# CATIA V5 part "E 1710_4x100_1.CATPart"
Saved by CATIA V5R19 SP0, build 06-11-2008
Part number: E 1710_4x100_1
Definition: E 1710_4x100_1
Nomenclature: E 1710_4x100_1
Source: Unknown
Description: PART-E 1710_4x100_1-DESC
Bounding box of the stored display mesh (mm): x -4 to 4, y -3.991 to 3.991, z 0 to 93.427
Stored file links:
  C:\Users\jsmid\Desktop\DP_Smidak_Forma LEGO\E 1710_4x100_1.CATPart
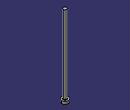
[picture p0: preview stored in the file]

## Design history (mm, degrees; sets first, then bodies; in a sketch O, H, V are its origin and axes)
Body1 "E 1710_4x100" (main body)
  Solid1: solid without history
  Sketch1 on face of Solid1, origin (0, 0, 100), H (1, 0, 0), V (0, 1, 0)
    circle A1 centre (0, 0) radius 3.1736
  Pocket1: profile Sketch1, direction (0, 0, -1), length 6.573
